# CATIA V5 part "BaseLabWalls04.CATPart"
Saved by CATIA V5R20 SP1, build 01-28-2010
Part number: BaseLabirinth
Bounding box of the stored display mesh (mm): x 0 to 180, y 0 to 180, z 0 to 23
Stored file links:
  C:\Users\elisf\Desktop\Elis\ENSINOFATEC\MAV5\DIP\Labirinto\Walls02\BaseLabWalls04.CATPart
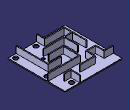
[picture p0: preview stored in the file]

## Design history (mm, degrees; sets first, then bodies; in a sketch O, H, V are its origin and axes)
Body1 (main body)
  Sketch1 on xy-plane, origin (0, 0, 0), H (1, 0, 0), V (0, 1, 0)
    line L1 (0, 0) -> (180, 0)
    line L2 (180, 0) -> (180, 180)
    line L3 (180, 180) -> (0, 180)
    line L4 (0, 180) -> (0, 0)
    length L1 = 180
    length L4 = 180
    horizontal: L1 H, L3 H
    vertical: L2 V, L4 V
  Pad1: profile Sketch1, direction (0, 0, 1), length 3
  Sketch2 on end face of Pad1, origin (0, 0, 3), H (1, 0, 0), V (0, 1, 0)
    reference projected line E1 (180, 180) -> (0, 180) from edge [face of Pad1 from Sketch1.L3 | end face of Pad1]
    point P3 (154, 0)
    line L1 (154, 0) -> (154, 100.5)
    line L2 (154, 100.5) -> (111, 100.5)
    line L3 (111, 100.5) -> (111, 97.5)
    line L4 (111, 97.5) -> (151, 97.5)
    line L5 (151, 97.5) -> (151, 0)
    point P8 (151, 0)
    line L6 (151, 0) -> (154, 0)
    line L7 (180, 126.5) -> (78, 126.5)
    line L8 (78, 126.5) -> (78, 72)
    line L9 (78, 72) -> (125, 72)
    line L10 (125, 72) -> (125, 75)
    line L11 (125, 75) -> (81, 75)
    line L12 (81, 75) -> (81, 123.5)
    line L13 (81, 123.5) -> (180, 123.5)
    line L14 (180, 123.5) -> (180, 126.5)
    point P17 (87, 0)
    line L15 (87, 0) -> (87, 23)
    line L16 (87, 23) -> (26, 23)
    line L17 (26, 23) -> (26, 95)
    line L18 (26, 95) -> (29, 95)
    line L19 (29, 95) -> (29, 52)
    line L20 (29, 52) -> (52, 52)
    line L21 (52, 52) -> (52, 95)
    point P24 (52, 95)
    line L22 (52, 95) -> (55, 95)
    line L23 (55, 95) -> (55, 52)
    point P26 (55, 52)
    line L24 (55, 52) -> (119, 52)
    line L25 (119, 52) -> (119, 49)
    line L26 (119, 49) -> (29, 49)
    point P29 (29, 49)
    line L27 (29, 49) -> (29, 26)
    line L28 (29, 26) -> (90, 26)
    line L29 (90, 26) -> (90, 0)
    point P32 (90, 0)
    line L30 (90, 0) -> (87, 0)
    point P33 (131, 180)
    line L31 (131, 180) -> (131, 149.5)
    line L32 (131, 149.5) -> (154, 149.5)
    line L33 (154, 149.5) -> (154, 152.5)
    line L34 (154, 152.5) -> (134, 152.5)
    line L35 (134, 152.5) -> (134, 180)
    point P38 (134, 180)
    line L36 (134, 180) -> (131, 180)
    point P39 (0, 149.5)
    line L37 (0, 149.5) -> (26, 149.5)
    point P40 (26, 149.5)
    line L38 (26, 149.5) -> (26, 122)
    line L39 (26, 122) -> (58, 122)
    line L40 (58, 122) -> (58, 149.5)
    point P43 (58, 149.5)
    line L41 (58, 149.5) -> (105, 149.5)
    line L42 (105, 149.5) -> (105, 152.5)
    line L43 (105, 152.5) -> (55, 152.5)
    line L44 (55, 152.5) -> (55, 125)
    line L45 (55, 125) -> (29, 125)
    point P48 (29, 125)
    line L46 (29, 125) -> (29, 152.5)
    point P49 (29, 152.5)
    line L47 (29, 152.5) -> (0, 152.5)
    point P50 (0, 152.5)
    line L48 (0, 152.5) -> (0, 149.5)
    projected line E2 (180, 0) -> (180, 180) from edge [face of Pad1 from Sketch1.L2 | end face of Pad1]
    length L37 = 26
    distance E1 L47 = 27.5
    length L48 = 3
    distance L42 L44 = 50
    distance L45 L39 = 3
    distance L46 L38 = 3
    distance L40 L44 = 3
    length L46 = 27.5
    length L36 = 3
    length L33 = 3
    length L35 = 27.5
    length L34 = 20
    distance E2 L31 = 49
    length L45 = 26
    distance L22 L39 = 27
    length L25 = 3
    length L20 = 23
    length L27 = 23
    distance L16 L28 = 3
    length L30 = 3
    length L15 = 23
    length L22 = 3
    length L26 = 90
    length L16 = 61
    length L14 = 3
    length L3 = 3
    length L10 = 3
    distance L12 L8 = 3
    length L6 = 3
    distance L1 E2 = 26
    distance L10 L5 = 26
    distance L8 L23 = 23
    distance L7 L32 = 23
    distance L2 L13 = 23
    distance L9 L24 = 20
    distance L3 L12 = 30
    coincidence: P3 H, P8 H, P17 H, P24 L18, P26 L20, P29 L19, P32 H, P33 E1, P38 E1, P39 V, P40 L17, P43 L37, P48 L19, P49 L43, P50 V, L14 E2
    vertical: L1 V, L3 V, L5 V, L8 V, L10 V, L12 V, L14 V, L15 V, L17 V, L19 V, L21 V, L23 V, L25 V, L27 V, L29 V, L31 V, L33 V, L35 V, L38 V, L40 V, L42 V, L44 V, L46 V, L48 V
    horizontal: L2 H, L4 H, L6 H, L7 H, L9 H, L11 H, L13 H, L16 H, L18 H, L20 H, L22 H, L24 H, L26 H, L28 H, L30 H, L32 H, L34 H, L36 H, L37 H, L39 H, L41 H, L43 H, L45 H, L47 H
  Pad2: profile Sketch2, direction (0, 0, 1), length 20
  Sketch3 on end face of Pad1, origin (0, 0, 3), H (1, 0, 0), V (0, 1, 0)
    circle A1 centre (42.194, 134) radius 5
    circle A2 centre (126.0441, 57.6019) radius 5
    circle A3 centre (122.8996, 141.3371) radius 7.5
    circle A4 centre (145.6129, 166.2822) radius 7.5
    circle A5 centre (13.5904, 137) radius 7.5
    circle A6 centre (94, 110.5) radius 7.5
    circle A7 centre (40.5, 63.3609) radius 7.5
    circle A8 centre (15.5, 19.7911) radius 7.5
    circle A9 centre (74.5, 10.5) radius 7.5
    circle A10 centre (103, 11.5) radius 7.5
    circle A11 centre (167.5, 12.5) radius 7.5
    circle A12 centre (167.2039, 111) radius 7.5
    reference projected line E1 (55, 125) -> (29, 125) from edge [face of Pad2 from Sketch2.L45 | end face of Pad2]
    reference projected line E2 (0, 149.5) -> (26, 149.5) from edge [face of Pad2 from Sketch2.L37 | end face of Pad2]
    reference projected point E3 (131, 149.5) from vertex [face of Pad2 from Sketch2.L32 | face of Pad2 from Sketch2.L31 | end face of Pad2]
    reference projected line E4 (81, 123.5) -> (180, 123.5) from edge [face of Pad2 from Sketch2.L13 | end face of Pad2]
    reference projected line E5 (81, 75) -> (81, 123.5) from edge [face of Pad2 from Sketch2.L12 | end face of Pad2]
    reference projected line E6 (81, 123.5) -> (180, 123.5) from edge [face of Pad2 from Sketch2.L13 | end face of Pad2]
    reference projected point E7 (119, 52) from vertex [face of Pad2 from Sketch2.L25 | face of Pad2 from Sketch2.L24 | end face of Pad2]
    reference projected line E8 (29, 52) -> (29, 95) from edge [face of Pad2 from Sketch2.L19 | end face of Pad2]
    reference projected line E9 (0, 0) -> (87, 0) from edge [face of Pad2 | end face of Pad1]
    reference projected line E12 (90, 0) -> (90, 26) from edge [face of Pad2 from Sketch2.L29 | end face of Pad2]
    reference projected line E13 (87, 23) -> (87, 0) from edge [face of Pad2 from Sketch2.L15 | end face of Pad2]
    reference projected line E14 (26, 23) -> (87, 23) from edge [face of Pad2 from Sketch2.L16 | end face of Pad2]
    reference projected line E15 (0, 180) -> (0, 0) from edge [face of Pad2 | end face of Pad1]
    reference projected line E16 (0, 0) -> (180, 0) from edge [face of Pad2 | end face of Pad1]
    reference projected line E17 (180, 0) -> (180, 180) from edge [face of Pad2 | end face of Pad1]
    radius A1 = 5
    radius A3 = 7.5
    distance A1 E1 = 4
    distance A5 E2 = 5
    distance E3 A3 = 4
    distance A6 E4 = 5.5
    distance A6 E5 = 5.5
    distance A12 E6 = 5
    distance A2 E7 = 4
    distance A7 E8 = 4
    distance A10 E9 = 4
    distance A10 E12 = 5.5
    distance A9 E13 = 5
    distance E14 A9 = 5
    distance A8 E15 = 8
    distance A11 E16 = 5
    distance A11 E17 = 5
  Pocket1: profile Sketch3, direction (0, 0, -1), length 3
